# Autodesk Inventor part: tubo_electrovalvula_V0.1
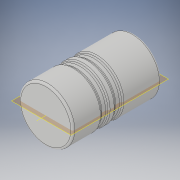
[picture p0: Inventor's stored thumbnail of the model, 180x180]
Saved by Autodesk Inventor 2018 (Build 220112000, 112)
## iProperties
Created: 2018-09
Part Number: tubo_electrovalvula_V0.1
Material: Generic
Document SubType Name: Modeling
Designer: Gordillo
Density: 1 g/cm^3
Appearance: Default
Author: Gordillo
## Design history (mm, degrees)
sketch "Sketch1"
  geometry: C1 r 55 at (0, 0); 1 further point
  constraints: 1 centre point, 1 coincident
  dimensions: "d0" = 110 diameter of C1
extrude "Extrusion1" new body sketch "Sketch1" distance "d1" = 180; taper "d2" = 0 deg
sketch "Sketch2"
  geometry: L1 (55, 180)-(-55, 180) reference; L2 (-55, 0)-(55, 0) reference; L3 (55, 0)-(55, 180) reference; L4 (55, 80)-(52, 80); L5 (52, 80)-(52, 92); L6 (52, 92)-(55, 92); L7 (55, 92)-(55, 80); L8 (55, 108)-(52, 108); L9 (52, 108)-(52, 120); L10 (52, 120)-(55, 120); L11 (55, 120)-(55, 108); L12 (0, -36)-(0, 216) reference; 1 further point
  constraints: 16 end point, 4 parallel, 2 horizontal, 2 perpendicular, 2 point on line
  dimensions: "d3" = 3 distance of L5.end L6.end; "d4" = 12 distance of L4.end L5.end; "d5" = 80 distance between parallel lines of L2 L4; "d6" = 3 distance of L9.end L10.end; "d7" = 12 distance of L8.end L9.end; "d8" = 16 distance between parallel lines of L8 L6
revolve "Revolution1" sketch "Sketch2" stored, may be unused: angle "d9" = 90 deg
fillet "Fillet1" dims "d10" = 4
body "Solid1"
node "Projected Loop1"
